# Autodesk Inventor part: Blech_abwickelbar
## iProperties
Created: 2010-03
Part Number: Blech_abwickelbar
Material: Aluminium - 6061
Document SubType Name: Sheet Metal
Designer: P.Tropf
Mass: 106.942 g
Surface Area: 806.156 cm^2
Volume: 39.4619 cm^3
Density: 2.71 g/cm^3
Sheet Metal Rule: Alu_1,0
Flat Pattern Width: 35 cm
Flat Pattern Length: 30 cm
Flat Pattern Area: 1050 cm^2
Author: P.Tropf
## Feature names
1. Spiegeln1 [Mirror]
2. Grobblech1
3. Grobblech2
4. Biegung1
5. Grobblech3
6. Biegung2
